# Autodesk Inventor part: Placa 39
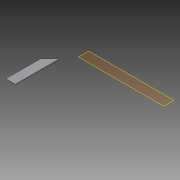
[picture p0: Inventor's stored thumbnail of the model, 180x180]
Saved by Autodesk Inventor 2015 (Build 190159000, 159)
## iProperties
Created: 2015-04
Part Number: Placa 39
Material: Generic
Document SubType Name: Modeling
Designer: suporte
Density: 1 g/cm^3
Appearance: Default
Author: suporte
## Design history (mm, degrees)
workplane "Work Plane1"
sketch "Sketch1"
  geometry: L1 (606.156, -970.868)-(-993.844, -970.868) reference; L2 (-843.844, -264.472)-(-843.844, -970.868) reference; L3 (-838.08, -258.713)-(-843.844, -264.472) reference; L4 (-712.207, 79.132)-(-993.844, -202.31) reference; L5 (-993.844, -202.31)-(-993.844, -1120.868) reference; L6 (-843.844, -264.472)-(-993.844, -414.368); L7 (-993.844, -414.368)-(-993.844, -970.868); L8 (-993.844, -970.868)-(-843.844, -970.868); L9 (-843.844, -970.868)-(-843.844, -264.472); 1 further point
  constraints: 8 end point, 3 collinear, 1 perpendicular, 1 point on line
extrude "Extrusion1" new body sketch "Sketch1" distance "d0" = 12.5; taper "d1" = 0 deg
body "Solid1"
node "Reference1"
node "Reference2"
node "Reference3"
node "Reference4"
node "Reference5"
